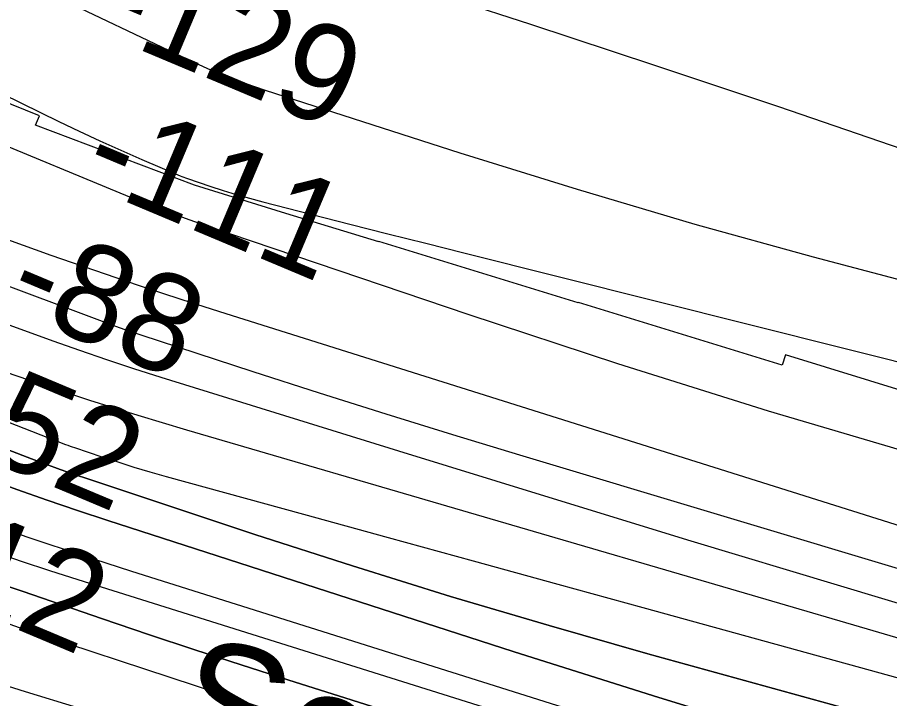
# Model space of a CAD drawing. Extents: x 3734862 to 3772949, y 391520 to 417239.
# Drawn here: x 3742730 to 3743330, y 405062 to 405530 of the extents above; entities that cross this region are included whole.
import ezdxf

# ---------------------------------------------------------------- set-up
doc = ezdxf.new("R2010")
doc.units = 0
for name, color, linetype in [('V-RIVR-EDGE', 7, 'Continuous'), ('V-RIVR-IDEN', 7, 'Continuous'), ('V-RIVR-RANG', 7, 'Continuous'), ('V-RRAP-RVMT', 7, 'Continuous'), ('V-TOPO-DPTH', 7, 'Continuous'), ('V-TOPO-MAJR', 7, 'Continuous'), ('V-TOPO-MINR', 7, 'Continuous'), ('V-TOPO-WATR', 7, 'Continuous')]:
    doc.layers.add(name, color=color, linetype=linetype)

msp = doc.modelspace()

# ---------------------------------------------------------------- linework, layer by layer
at = {"layer": 'V-RIVR-EDGE'}
msp.add_spline([(3740284.23, 406091.5), (3740310.88, 406078.89), (3740348.85, 406061.82), (3740353.7, 406060.59), (3740364.62, 406059.35), (3740372.7, 406056.5), (3740387.63, 406044.33), (3740395.71, 406041.89), (3740409.04, 406036.6), (3740430.04, 406026.44), (3740442.56, 406019.13), (3740451.45, 406015.46), (3740466, 406012.6), (3740476.5, 406010.15), (3740489.43, 406005.67), (3740507.61, 405997.13), (3740522.95, 405989), (3740544.36, 405977.63), (3740556.47, 405971.53), (3740569.81, 405967.86), (3740577.49, 405966.22), (3740592.04, 405964.57), (3740596.89, 405964.56), (3740607.4, 405960.08), (3740616.68, 405953.19), (3740635.67, 405946.27), (3740666.77, 405930.82), (3740697.87, 405917.81), (3740711.61, 405913.73), (3740727.77, 405908.03), (3740737.46, 405903.96), (3740772.6, 405884.87), (3740794.41, 405876.73), (3740819.46, 405866.96), (3740836.42, 405858.83), (3740859.04, 405847.05), (3740882.05, 405833.24), (3740901.84, 405822.28), (3740929.3, 405808.05), (3740946.26, 405798.31), (3740968.88, 405787.33), (3740998.36, 405770.68), (3741025.41, 405754.04), (3741050.85, 405741.44), (3741073.47, 405730.06), (3741090.84, 405721.93), (3741112.25, 405712.98), (3741151.03, 405698.33), (3741164.76, 405692.23), (3741182.94, 405682.88), (3741205.16, 405675.14), (3741229.4, 405665.78), (3741250.81, 405658.45), (3741277.48, 405649.89), (3741303.74, 405640.12), (3741333.23, 405627.52), (3741357.46, 405614.92), (3741386.54, 405602.72), (3741400.29, 405601.07), (3741418.87, 405593.74), (3741447.55, 405583.56), (3741468.56, 405576.63), (3741486.74, 405569.72), (3741500.88, 405562.4), (3741512.59, 405556.71), (3741522.69, 405552.64), (3741537.24, 405548.56), (3741581.27, 405532.28), (3741608.74, 405519.68), (3741642.25, 405499.78), (3741662.84, 405486.79), (3741679, 405477.85), (3741697.17, 405467.7), (3741715.33, 405455.12), (3741729.87, 405447.8), (3741754.11, 405435.61), (3741802.57, 405410.02), (3741822.76, 405401.07), (3741865.57, 405380.34), (3741892.23, 405366.12), (3741915.66, 405356.36), (3741930.6, 405350.26), (3741951.21, 405343.33), (3741972.63, 405337.62), (3742009, 405331.06), (3742028.4, 405323.73), (3742041.72, 405317.23), (3742042.52, 405313.99), (3742046.97, 405311.15), (3742058.68, 405307.89), (3742068.79, 405307.86), (3742073.65, 405307.85), (3742079.72, 405310.67), (3742088.62, 405312.26), (3742095.08, 405310.22), (3742118.51, 405300.06), (3742134.27, 405294.76), (3742159.72, 405286.61), (3742182.35, 405279.28), (3742201.34, 405273.97), (3742222.36, 405268.26), (3742239.73, 405262.15), (3742263.56, 405253.19), (3742278.91, 405245.07), (3742307.99, 405229.63), (3742326.16, 405219.48), (3742346.35, 405209.72), (3742373.82, 405199.55), (3742400.89, 405188.16), (3742413.41, 405180.44), (3742429.96, 405170.29), (3742436, 405161.79), (3742439.22, 405154.9), (3742444.47, 405149.63), (3742450.53, 405147.6), (3742468.31, 405143.91), (3742478.41, 405141.06), (3742497.4, 405134.14), (3742510.32, 405128.04), (3742527.69, 405119.91), (3742545.06, 405110.97), (3742567.68, 405100.4), (3742590.7, 405089.83), (3742639.16, 405063.83), (3742649.27, 405062.19), (3742658.97, 405062.16), (3742667.46, 405062.55), (3742676.76, 405060.5), (3742690.9, 405056.02), (3742714.33, 405045.85), (3742740.98, 405032.04), (3742759.96, 405022.29), (3742790.25, 405004.82), (3742814.09, 404997.08), (3742826.61, 404993.01), (3742844.39, 404988.11), (3742862.98, 404984.02), (3742878.74, 404979.94), (3742899.75, 404972.2), (3742910.66, 404970.15), (3742935.31, 404961.6), (3742961.17, 404953.85), (3742978.54, 404947.34), (3742993.89, 404940.02), (3743010.45, 404933.92), (3743026.22, 404931.45), (3743054.51, 404925.72), (3743082.4, 404921.61), (3743104.23, 404917.51), (3743119.99, 404913.83), (3743140.19, 404908.12), (3743171.31, 404899.96), (3743202.02, 404891.79), (3743227.88, 404884.05), (3743293.35, 404868.11)], degree=3, dxfattribs=at)
at = {"layer": 'V-RRAP-RVMT'}
for p, q in [((3742745.5, 405462.47), (3742615.08, 405516.01)), ((3742742.94, 405456.22), (3742745.5, 405462.47)), ((3742852.06, 405414.97), (3742742.94, 405456.22)), ((3742914.96, 405395.43), (3742852.06, 405414.97)), ((3742978.69, 405375.98), (3742914.96, 405395.43)), ((3742978.78, 405376.26), (3742978.69, 405375.98)), ((3743115.79, 405334.05), (3742978.78, 405376.26)), ((3743115.86, 405334.29), (3743115.79, 405334.05)), ((3743255.86, 405291.14), (3743115.86, 405334.29)), ((3743258.09, 405298.36), (3743255.86, 405291.14)), ((3743398.42, 405255.11), (3743258.09, 405298.36))]:
    msp.add_line(p, q, dxfattribs=at)
at = {"layer": 'V-TOPO-DPTH'}
for points in [[(3743361.03, 405005.12), (3743264.08, 405033.99), (3743167.44, 405063.88), (3743071, 405094.46), (3742792.58, 405184.37), (3742771.64, 405191.29), (3742750.77, 405198.39), (3742729.99, 405205.77), (3742709.28, 405213.33), (3742484.84, 405297.03), (3742386.12, 405334.26), (3742287.59, 405371.99), (3742189.35, 405410.46), (3742091.3, 405449.43), (3741929.98, 405514.23), (3741912.74, 405521.18), (3741895.5, 405528.15), (3741878.28, 405535.15), (3741861.07, 405542.17), (3741377.23, 405740.01)], [(3741377.23, 405740.01), (3741861.07, 405542.17), (3741878.28, 405535.15), (3741895.5, 405528.15), (3741912.74, 405521.18), (3741929.98, 405514.23), (3742091.3, 405449.43), (3742189.35, 405410.46), (3742287.59, 405371.99), (3742386.12, 405334.26), (3742484.84, 405297.03), (3742709.28, 405213.33), (3742729.99, 405205.77), (3742750.77, 405198.39), (3742771.64, 405191.29), (3742792.58, 405184.37), (3743071, 405094.46), (3743167.44, 405063.88), (3743264.08, 405033.99), (3743361.03, 405005.12)], [(3741363.16, 405717.5), (3741827.93, 405528.13), (3741856.94, 405516.34), (3741885.97, 405504.59), (3741915.03, 405492.89), (3741944.1, 405481.24), (3742432.63, 405285.91), (3742483.41, 405265.92), (3742534.33, 405246.28), (3742585.45, 405227.17), (3742636.7, 405208.43), (3742670.87, 405196.13), (3742705.21, 405184), (3742739.64, 405172.15), (3742774.21, 405160.71), (3742808.87, 405149.55), (3743464.89, 404942.66)], [(3741363.16, 405717.5), (3741827.93, 405528.13), (3741856.94, 405516.34), (3741885.97, 405504.59), (3741915.03, 405492.89), (3741944.1, 405481.24), (3742432.63, 405285.91), (3742483.41, 405265.92), (3742534.33, 405246.28), (3742585.45, 405227.17), (3742636.7, 405208.43), (3742670.87, 405196.13), (3742705.21, 405184), (3742739.64, 405172.15), (3742774.21, 405160.71), (3742808.87, 405149.55), (3743464.89, 404942.66)], [(3741411.34, 405617.14), (3741807.19, 405443.51), (3741830.17, 405433.47), (3741853.19, 405423.5), (3741876.24, 405413.61), (3741899.31, 405403.78), (3742430.07, 405178.87), (3742474.44, 405160.54), (3742519.01, 405142.74), (3742563.9, 405125.75), (3742608.99, 405109.29), (3742628.6, 405102.33), (3742664.14, 405090.04), (3742699.81, 405078.13), (3742735.66, 405066.8), (3742771.64, 405055.85), (3743259.3, 404911.76), (3743317.23, 404894.56), (3743375.12, 404877.24)], [(3743608.54, 404969.82), (3743163.59, 405092.85), (3743095.73, 405112.17), (3743028.08, 405132.16), (3742960.74, 405153.18), (3742893.61, 405174.88), (3742779.49, 405212.72), (3742769.6, 405216.08), (3742759.74, 405219.53), (3742749.93, 405223.12), (3742740.15, 405226.81), (3742102.5, 405472.6), (3742069.45, 405485.43), (3742036.43, 405498.35), (3742003.47, 405511.42), (3741970.56, 405524.59), (3741916.27, 405546.44), (3741910.52, 405548.76), (3741904.78, 405551.08), (3741899.03, 405553.4), (3741893.29, 405555.73), (3741793.51, 405596.2)], [(3743608.54, 404969.82), (3743163.59, 405092.85), (3743095.73, 405112.17), (3743028.08, 405132.16), (3742960.74, 405153.18), (3742893.61, 405174.88), (3742779.49, 405212.72), (3742769.6, 405216.08), (3742759.74, 405219.53), (3742749.93, 405223.12), (3742740.15, 405226.81), (3742102.5, 405472.6), (3742069.45, 405485.43), (3742036.43, 405498.35), (3742003.47, 405511.42), (3741970.56, 405524.59), (3741916.27, 405546.44), (3741910.52, 405548.76), (3741904.78, 405551.08), (3741899.03, 405553.4), (3741893.29, 405555.73), (3741793.51, 405596.2)], [(3743596.77, 404859.69), (3742916.13, 405074.9), (3742884.22, 405085.11), (3742852.37, 405095.48), (3742820.59, 405106.08), (3742788.86, 405116.83), (3742733.58, 405135.79), (3742729.54, 405137.21), (3742725.52, 405138.66), (3742721.52, 405140.18), (3742717.53, 405141.73), (3742484.8, 405234.36), (3742383.16, 405274.86), (3742281.54, 405315.42), (3742179.96, 405356.06), (3742078.4, 405396.76), (3741883.69, 405474.87), (3741879.5, 405476.55), (3741875.31, 405478.22), (3741871.12, 405479.9), (3741866.93, 405481.58), (3741806.92, 405505.55), (3741772.71, 405519.18)], [(3743596.77, 404859.69), (3742916.13, 405074.9), (3742884.22, 405085.11), (3742852.37, 405095.48), (3742820.59, 405106.08), (3742788.86, 405116.83), (3742733.58, 405135.79), (3742729.54, 405137.21), (3742725.52, 405138.66), (3742721.52, 405140.18), (3742717.53, 405141.73), (3742484.8, 405234.36), (3742383.16, 405274.86), (3742281.54, 405315.42), (3742179.96, 405356.06), (3742078.4, 405396.76), (3741883.69, 405474.87), (3741879.5, 405476.55), (3741875.31, 405478.22), (3741871.12, 405479.9), (3741866.93, 405481.58), (3741806.92, 405505.55), (3741772.71, 405519.18)]]:
    msp.add_lwpolyline(points, dxfattribs=at)
at = {"layer": 'V-TOPO-MAJR'}
for points in [[(3741173.2, 406092.75), (3741984.41, 405747.97), (3742807.36, 405407), (3742820.91, 405401.54), (3742834.53, 405396.26), (3742848.26, 405391.25), (3742862.05, 405386.42), (3743039.82, 405326.16), (3743142.84, 405292.3), (3743246.26, 405259.73), (3743350.26, 405229.09), (3743454.66, 405199.74), (3743671.51, 405140.96), (3743703.12, 405132.34), (3743734.71, 405123.68), (3743766.29, 405114.93), (3743797.84, 405106.13), (3743838.8, 405094.66), (3743890.8, 405079.98), (3743942.76, 405065.18), (3743994.66, 405050.18), (3744046.53, 405035.05), (3744456.13, 404914.76)], [(3742643.51, 405283.73), (3742763.54, 405236.74), (3742765.04, 405236.17), (3742766.56, 405235.61), (3742768.08, 405235.07), (3742769.6, 405234.54), (3742788.42, 405228.21), (3742799.39, 405224.63), (3742810.39, 405221.17), (3742821.46, 405217.9), (3742832.56, 405214.75), (3742926.92, 405188.84), (3742985.22, 405172.82), (3743043.52, 405156.79), (3743101.82, 405140.73), (3743160.11, 405124.66), (3743532.3, 405022)]]:
    msp.add_lwpolyline(points, dxfattribs=at)
at = {"layer": 'V-TOPO-MINR'}
for points in [[(3741117.9, 405937.86), (3741894.7, 405632.82), (3741913.32, 405625.51), (3741931.93, 405618.2), (3741950.54, 405610.89), (3741969.15, 405603.59), (3742125.97, 405542.03), (3742223.13, 405504.32), (3742320.49, 405467.11), (3742418.12, 405430.66), (3742515.95, 405394.7), (3742754.75, 405307.96), (3742773.18, 405301.41), (3742791.68, 405295.04), (3742810.26, 405288.93), (3742828.9, 405283), (3742992.21, 405232.3), (3743092.6, 405201.3), (3743193.05, 405170.53), (3743293.6, 405140.07), (3743394.22, 405109.84)], [(3742031.22, 405816.28), (3742758.77, 405458.79), (3742772.91, 405451.97), (3742787.13, 405445.32), (3742801.45, 405438.89), (3742815.84, 405432.61), (3742842.28, 405421.33), (3742843.51, 405420.82), (3742844.74, 405420.33), (3742845.99, 405419.87), (3742847.24, 405419.44), (3742862.72, 405414.23), (3742871.74, 405411.31), (3742880.81, 405408.52), (3742889.94, 405405.94), (3742899.1, 405403.48), (3742932.85, 405394.85), (3742958.93, 405388.2), (3742985.01, 405381.57), (3743011.1, 405374.98), (3743037.19, 405368.41), (3743430.7, 405269.56)], [(3741768.7, 405754), (3741888.15, 405706.73), (3741922.45, 405693.15), (3741956.75, 405679.58), (3741991.05, 405666.01), (3742025.35, 405652.44), (3742634.65, 405411.39), (3742664.19, 405399.89), (3742693.82, 405388.6), (3742723.56, 405377.64), (3742753.39, 405366.88), (3742783.32, 405356.45), (3742813.33, 405346.23), (3742843.45, 405336.33), (3742873.64, 405326.65), (3743710.15, 405063.08), (3744491.27, 404811.88)], [(3741377.23, 405740.01), (3741861.07, 405542.17), (3741878.28, 405535.15), (3741895.5, 405528.15), (3741912.74, 405521.18), (3741929.98, 405514.23), (3742091.3, 405449.43), (3742189.35, 405410.46), (3742287.59, 405371.99), (3742386.12, 405334.26), (3742484.84, 405297.03), (3742709.28, 405213.33), (3742729.99, 405205.77), (3742750.77, 405198.39), (3742771.64, 405191.29), (3742792.58, 405184.37), (3743071, 405094.46), (3743167.44, 405063.88), (3743264.08, 405033.99), (3743361.03, 405005.12)], [(3741587.56, 405728.15), (3741862.86, 405619.25), (3741892.81, 405607.4), (3741922.76, 405595.55), (3741952.72, 405583.7), (3741982.67, 405571.85), (3742458.88, 405383.5), (3742511.92, 405362.88), (3742565.12, 405342.69), (3742618.56, 405323.13), (3742672.15, 405304), (3742713.7, 405289.44), (3742746.72, 405278.16), (3742779.86, 405267.23), (3742813.15, 405256.83), (3742846.56, 405246.77), (3743244.78, 405130.27), (3743318.14, 405108.75), (3743391.48, 405087.16)], [(3741363.16, 405717.5), (3741827.93, 405528.13), (3741856.94, 405516.34), (3741885.97, 405504.59), (3741915.03, 405492.89), (3741944.1, 405481.24), (3742432.63, 405285.91), (3742483.41, 405265.92), (3742534.33, 405246.28), (3742585.45, 405227.17), (3742636.7, 405208.43), (3742670.87, 405196.13), (3742705.21, 405184), (3742739.64, 405172.15), (3742774.21, 405160.71), (3742808.87, 405149.55), (3743464.89, 404942.66)], [(3741791.59, 405701.13), (3741927.36, 405646.92), (3741934.33, 405644.15), (3741941.3, 405641.38), (3741948.29, 405638.64), (3741955.27, 405635.9), (3742012.84, 405613.42), (3742048.64, 405599.53), (3742084.47, 405585.73), (3742120.36, 405572.07), (3742156.29, 405558.51), (3742786.72, 405322.02), (3742793.82, 405319.41), (3742800.94, 405316.86), (3742808.09, 405314.41), (3742815.26, 405312.02), (3742892.15, 405286.93), (3742937.83, 405272.2), (3742983.58, 405257.69), (3743029.44, 405243.51), (3743075.36, 405229.55), (3743627.85, 405063.71)], [(3743338.42, 405439.62), (3743253.54, 405468.65), (3743168.48, 405497.15), (3743083.3, 405525.29), (3742981.1, 405558.7), (3742946.84, 405569.57), (3742912.47, 405580.06), (3742877.93, 405589.96), (3742843.27, 405599.48), (3742597.85, 405664.63)], [(3742586.02, 405625.98), (3742848.25, 405500.97), (3742861.1, 405495.16), (3742874.09, 405489.7), (3742887.28, 405484.77), (3742900.62, 405480.2), (3743034.45, 405437.24), (3743115.02, 405412.2), (3743195.88, 405388.15), (3743277.16, 405365.59), (3743358.74, 405344.03)], [(3741793.51, 405596.2), (3741893.29, 405555.73), (3741899.03, 405553.4), (3741904.78, 405551.08), (3741910.52, 405548.76), (3741916.27, 405546.44), (3741970.56, 405524.59), (3742003.47, 405511.42), (3742036.43, 405498.35), (3742069.45, 405485.43), (3742102.5, 405472.6), (3742740.15, 405226.81), (3742749.93, 405223.12), (3742759.74, 405219.53), (3742769.6, 405216.08), (3742779.49, 405212.72), (3742893.61, 405174.88), (3742960.74, 405153.18), (3743028.08, 405132.16), (3743095.73, 405112.17), (3743163.59, 405092.85), (3743608.54, 404969.82)], [(3741692.35, 405567.73), (3741809.95, 405520.32), (3741845.38, 405506.06), (3741880.82, 405491.84), (3741916.28, 405477.67), (3741951.75, 405463.53), (3742618.12, 405198.49), (3742637.12, 405191.06), (3742656.16, 405183.78), (3742675.29, 405176.71), (3742694.48, 405169.79), (3742713.74, 405163.08), (3742733.05, 405156.51), (3742752.42, 405150.14), (3742771.85, 405143.92), (3743202.02, 405008.69), (3743273.88, 404986.1), (3743345.75, 404963.52)], [(3741772.71, 405519.18), (3741806.92, 405505.55), (3741866.93, 405481.58), (3741871.12, 405479.9), (3741875.31, 405478.22), (3741879.5, 405476.55), (3741883.69, 405474.87), (3742078.4, 405396.76), (3742179.96, 405356.06), (3742281.54, 405315.42), (3742383.16, 405274.86), (3742484.8, 405234.36), (3742717.53, 405141.73), (3742721.52, 405140.18), (3742725.52, 405138.66), (3742729.54, 405137.21), (3742733.58, 405135.79), (3742788.86, 405116.83), (3742820.59, 405106.08), (3742852.37, 405095.48), (3742884.22, 405085.11), (3742916.13, 405074.9), (3743596.77, 404859.69)], [(3741787.53, 405489.65), (3741827.02, 405473.07), (3741866.5, 405456.43), (3741905.93, 405439.7), (3741945.34, 405422.91), (3741965.8, 405414.17), (3742015.5, 405393.19), (3742065.33, 405372.5), (3742115.34, 405352.25), (3742165.47, 405332.29), (3742685.11, 405128.07), (3742700.56, 405122.15), (3742716.07, 405116.4), (3742731.68, 405110.92), (3742747.36, 405105.61), (3742922.93, 405047.76), (3743026.53, 405013.93), (3743130.23, 404980.45), (3743234.11, 404947.51), (3743338.11, 404914.92)]]:
    msp.add_lwpolyline(points, dxfattribs=at)
at = {"layer": 'V-TOPO-WATR'}
msp.add_lwpolyline([(3741411.34, 405617.14), (3741807.19, 405443.51), (3741830.17, 405433.47), (3741853.19, 405423.5), (3741876.24, 405413.61), (3741899.31, 405403.78), (3742430.07, 405178.87), (3742474.44, 405160.54), (3742519.01, 405142.74), (3742563.9, 405125.75), (3742608.99, 405109.29), (3742628.6, 405102.33), (3742664.14, 405090.04), (3742699.81, 405078.13), (3742735.66, 405066.8), (3742771.64, 405055.85), (3743259.3, 404911.76), (3743317.23, 404894.56), (3743375.12, 404877.24)], dxfattribs=at)

# ---------------------------------------------------------------- texts
at = {"layer": 'V-RIVR-IDEN'}
msp.add_text('September', height=83, rotation=345.16554, dxfattribs=at).set_placement((3742832.62, 405026.59))
at = {"layer": 'V-RIVR-RANG'}
for s, p in [('-129', (3742782.75, 405521.34)), ('-111', (3742771.98, 405417.4)), ('-88', (3742720.12, 405330.72)), ('-52', (3742678.22, 405239.86)), ('-12', (3742653.83, 405141.64))]:
    msp.add_text(s, height=67, rotation=337.20058, dxfattribs=at).set_placement(p)

doc.saveas('drawing.dxf')
